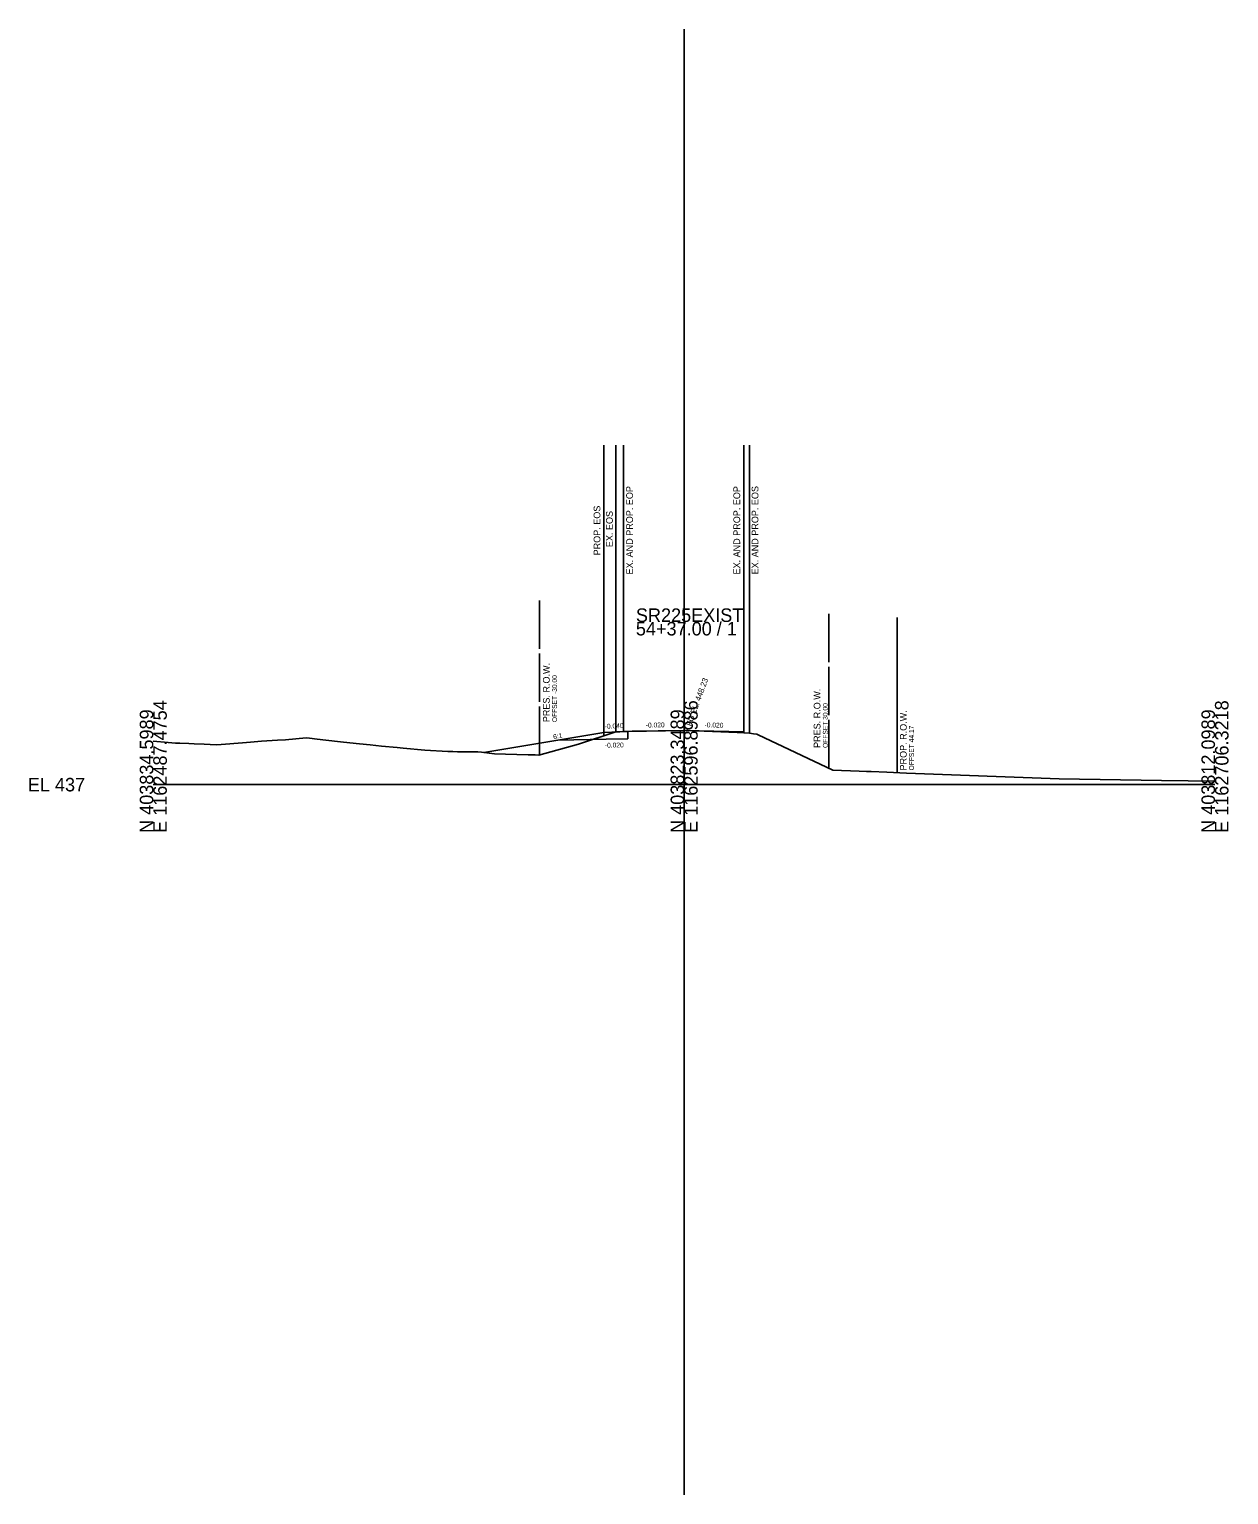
# Model space of a CAD drawing. Extents: x -26 to 246, y -78 to 2098.
# Drawn here: x -25.7 to 222.8, y 352.8 to 656.5 of the extents above; entities that cross this region are included whole.
import ezdxf

# ---------------------------------------------------------------- set-up
doc = ezdxf.new("R2010")
doc.units = 0
for name, color, linetype in [('DESIGN - SCRATCH - User 1', 7, 'Continuous'), ('DESIGN - SCRATCH - User 2', 7, 'Continuous'), ('DESIGN - SHEET - Light Grid', 7, 'Continuous'), ('SURVEY - GROUND - Top of Ground', 7, 'Continuous')]:
    doc.layers.add(name, color=color, linetype=linetype)

msp = doc.modelspace()

# ---------------------------------------------------------------- linework, layer by layer
at = {"layer": 'DESIGN - SCRATCH - User 1'}
for p, q in [((93.39, 510.15), (93.39, 570.35)), ((95.86, 510.97), (95.86, 570.35)), ((97.46, 511.05), (97.46, 570.35)), ((122.36, 510.73), (122.36, 570.35)), ((123.56, 510.68), (123.56, 570.35)), ((80, 528.17), (80, 538.17)), ((140, 525.41), (140, 535.41)), ((154.17, 502.49), (154.17, 534.65)), ((80, 517.17), (80, 527.17)), ((140, 514.41), (140, 524.41)), ((80, 506.17), (80, 516.17)), ((140, 503.41), (140, 513.41)), ((93.39, 510.8), (83.84, 509.21)), ((98.33, 511), (93.39, 510.8)), ((110, 511.23), (98.33, 511)), ((98.33, 511), (98.33, 509.5)), ((110, 511.23), (122.36, 510.98)), ((122.36, 510.98), (122.36, 510.74)), ((83.84, 509.21), (68.5, 506.65)), ((93.83, 509.41), (83.84, 509.21)), ((98.33, 509.5), (93.83, 509.41))]:
    msp.add_line(p, q, dxfattribs=at)
at = {"layer": 'DESIGN - SCRATCH - User 2'}
msp.add_line((110, 352.85), (110, 656.54), dxfattribs=at)
at = {"layer": 'DESIGN - SHEET - Light Grid'}
for p, q in [((110, 500), (110, 533.72)), ((0, 500), (110, 500)), ((110, 500), (220, 500))]:
    msp.add_line(p, q, dxfattribs=at)
at = {"layer": 'SURVEY - GROUND - Top of Ground'}
msp.add_lwpolyline([(0, 509.01), (3.1, 508.76), (4.57, 508.62), (5.49, 508.57), (7.33, 508.52), (8.49, 508.47), (10.51, 508.4), (13.01, 508.28), (14.04, 508.35), (18.45, 508.68), (20.16, 508.81), (22.44, 508.98), (25.76, 509.24), (27.41, 509.26), (31.68, 509.71), (32.4, 509.61), (33.98, 509.43), (38.15, 508.94), (39.43, 508.81), (42.73, 508.43), (44.93, 508.22), (47.27, 507.96), (50.5, 507.67), (51.76, 507.53), (56.26, 507.14), (61.03, 506.88), (62.09, 506.85), (63.05, 506.82), (67.28, 506.8), (67.98, 506.71), (70.69, 506.38), (72.96, 506.31), (77.65, 506.19), (79.14, 506.15), (79.87, 506.13), (88.08, 508.4), (95.86, 510.97), (97.46, 511.05), (99.23, 511.08), (110, 511.23), (110.78, 511.24), (120.99, 510.79), (122.36, 510.74), (123.56, 510.68), (124.39, 510.55), (125.05, 510.45), (125.37, 510.3), (140.82, 503.02), (146.27, 502.77), (147.76, 502.7), (148.75, 502.72), (151.99, 502.57), (156.06, 502.41), (187.72, 501.23), (208.9, 500.89), (220, 500.71)], dxfattribs=at)

# ---------------------------------------------------------------- texts
at = {"layer": 'DESIGN - SCRATCH - User 1'}
for s, height, rotation, p in [(' EX. AND PROP. EOP', 1.4, 90, (99.39, 543.05)), (' EX. AND PROP. EOP', 1.4, 90, (121.61, 543.05)), (' EX. AND PROP. EOS', 1.4, 90, (125.39, 543.06)), ('PRES. R.O.W.', 1.4, 90, (82.15, 512.95)), ('OFFSET -30.00', 1, 90, (83.65, 512.95)), ('  FG EL. 448.23', 1.2, 70, (111.15, 511.2)), ('PRES. R.O.W.', 1.4, 90, (138.25, 507.61)), ('OFFSET 30.00', 1, 90, (139.75, 507.61)), ('PROP. R.O.W.', 1.4, 90, (156.12, 502.94)), ('6:1', 1, 9.4623, (82.94, 509.42)), ('-0.040', 1, 2.2906, (93.56, 511.58)), ('-0.020', 1, 1.1458, (102.06, 511.82)), ('-0.020', 1, 358.8542, (114.22, 511.89)), ('OFFSET 44.17', 1, 90, (157.62, 502.94)), ('-0.020', 1, 1.1458, (93.58, 507.66))]:
    msp.add_text(s, height=height, rotation=rotation, dxfattribs=at).set_placement(p)
at = {"layer": 'DESIGN - SCRATCH - User 2'}
for s, p in [('PROP. EOS', (92.64, 547.52)), (' EX. EOS', (95.22, 548.71))]:
    msp.add_text(s, height=1.4, rotation=90, dxfattribs=at).set_placement(p)
at = {"layer": 'DESIGN - SHEET - Light Grid'}
for s, p in [('SR225EXIST', (100, 533.72)), ('54+37.00 / 1', (100, 530.92)), ('EL 437', (-26, 498.6))]:
    msp.add_text(s, height=2.8, dxfattribs=at).set_placement(p)
for s, p in [('E 1162487.4754', (2.8, 490)), ('E 1162596.8986', (112.8, 490)), ('E 1162706.3218', (222.8, 490)), ('N 403834.5989', (0, 490)), ('N 403823.3489', (110, 490)), ('N 403812.0989', (220, 490))]:
    msp.add_text(s, height=2.8, rotation=90, dxfattribs=at).set_placement(p)

doc.saveas('drawing.dxf')
